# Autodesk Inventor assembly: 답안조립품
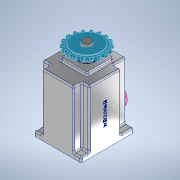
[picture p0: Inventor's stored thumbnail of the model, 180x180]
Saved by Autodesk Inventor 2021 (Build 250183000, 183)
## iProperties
Created: 2022-08
Part Number: 답안조립품
Document SubType Name: Assembly
Designer: Owner
Author: Owner
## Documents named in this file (16)
- C:\Users\Owner\Desktop\720810V1018\답안조립품.iam
- C:\Users\Owner\Desktop\720810V1018\본체.ipt
- C:\Users\Owner\Desktop\720810V1018\멈춤나사 M3.ipt
- C:\Users\Owner\Desktop\720810V1018\메인 축.ipt
- C:\Users\Owner\Desktop\720810V1018\베어링 608.ipt
- C:\Users\Owner\Desktop\720810V1018\베어링 6003.ipt
- C:\Users\Owner\Desktop\720810V1018\볼트 M4 x 10.ipt
- C:\Users\Owner\Desktop\720810V1018\부시.ipt
- C:\Users\Owner\Desktop\720810V1018\상부 캡.ipt
- C:\Users\Owner\Desktop\720810V1018\서브 축.ipt
- C:\Users\Owner\Desktop\720810V1018\스프로킷.ipt
- C:\Users\Owner\Desktop\720810V1018\슬라이더.ipt
- C:\Users\Owner\Desktop\720810V1018\오일 실 8 x 22 x 7.ipt
- C:\Users\Owner\Desktop\720810V1018\오일 실 17 x 32 x 8.ipt
- C:\Users\Owner\Desktop\720810V1018\커버.ipt
- C:\Users\Owner\Desktop\720810V1018\키 5 x 5.ipt
